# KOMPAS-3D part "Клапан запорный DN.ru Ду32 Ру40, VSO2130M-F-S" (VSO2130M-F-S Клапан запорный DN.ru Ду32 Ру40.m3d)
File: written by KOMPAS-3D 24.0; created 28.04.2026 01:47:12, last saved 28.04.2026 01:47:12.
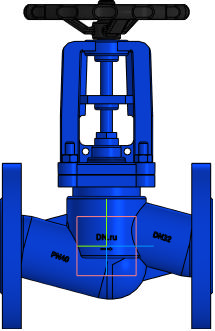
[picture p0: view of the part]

Document properties: Автор: DN.ru; Полное имя файла: C:\Работа\ГОТОВЫЕ ИСХОДНИКИ\VSO2130M-F-S Клапан запорный сильфонный DN.ru Ду15-100 Ру40\DN32\VSO2130M-F-S Клапан запорный DN.ru Ду32 Ру40.m3d

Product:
- Part/product: Клапан запорный DN.ru Ду32 Ру40  | designation VSO2130M-F-S
    Масса: 8
    Раздел спецификации: Прочие изделия
    Примечание: D090-01973

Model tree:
1. Операция без истории:1

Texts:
  VSO2130M-F-S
